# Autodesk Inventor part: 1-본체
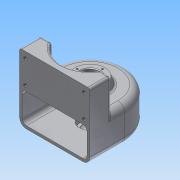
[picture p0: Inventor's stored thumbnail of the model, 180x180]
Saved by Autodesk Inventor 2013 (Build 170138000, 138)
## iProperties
Created: 2015-02
Part Number: 1-본체
Material: 알루미늄 6061
Document SubType Name: Modeling
Designer: Administrator
Density: 2.71 g/cm^3
Mass: 575.526 g
Surface Area: 706.56 cm^2
Volume: 212.371 cm^3
Author: Administrator
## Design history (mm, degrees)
sketch "스케치1" dims "d0" = 50
  geometry: L1 (50, 0)-(-50, 0); L2 (-50, 0)-(-50, -50); L3 (-50, -50)-(50, -50); L4 (50, -50)-(50, 0); 3 further points
  constraints: 8 end point, 2 coincident, 2 parallel, 1 horizontal, 1 horizontal alignment, 1 midpoint, 1 perpendicular, 2 other
  dimensions: "d3" = 50 distance of L3.end L1.start
extrude "돌출1" new body sketch "스케치1" distance "d4" = 50; taper "d5" = 0 deg
fillet "모깎기1" dims "d6" = 10
feature "쉘1" dims "d7" = 4
node "작업 평면1"
sketch "스케치2"
  geometry: L1 (-50, 0)-(-50, -50) reference; L2 (50, -50)-(50, 0) reference; L3 (50, -50)-(40, -50) reference; L4 (50, -50)-(-50, -50); L5 (-50, -50)-(-50, -20); L6 (50, -20)-(50, -50); L7 (-50, -20)-(-34.641, -20); L8 (34.641, -20)-(50, -20); A1 r 40 centre (0, 0) between (-34.641, -20) and (34.641, -20); 1 further point
  constraints: 10 end point, 3 parallel, 2 point on circle, 1 centre point, 1 coincident, 1 collinear, 1 horizontal, 1 perpendicular, 1 point on line
  dimensions: "d9" = 40 radius of A1; "d11" = 30 distance of L4.end L5.end
extrude "돌출2" join sketch "스케치2" stored distance "d12" = 50; taper "d13" = 0 deg
sketch "스케치3"
  geometry: C1 r 25 at (0, 0); A1 r 40 centre (0, 0) between (-34.641, -20) and (34.641, -20) reference
  constraints: 1 centre point, 1 coincident
  dimensions: "d14" = 50 diameter of C1
extrude "돌출3" join sketch "스케치3" distance "d16" = 10; taper "d17" = -20 deg
sketch "스케치4"
  geometry: C1 r 20 at (0, 0); A1 r 40 centre (0, 0) between (40, 0) and (-40, 0) reference
  constraints: 1 centre point, 1 coincident
  dimensions: "d18" = 40 diameter of C1
extrude "돌출4" join sketch "스케치4" distance "d20" = 9; taper "d21" = 0 deg
hole "구멍1" diameter "d24" = 20; stored, may be unused: countersink angle "d28" = 90 deg, drill point angle "d30" = 118 deg; dims "d22" = 10, "d23" = 10, "d25" = 6, "d26" = 28, "d27" = 10, "d29" = 8
sketch "스케치5"
  geometry: C1 r 20 at (0, 0) reference; A1 r 40 centre (0, 0) between (40, 0) and (-40, 0) reference
hole "구멍2" sketch "스케치5" at (0, 0) diameter "d31" = 20; stored, may be unused: countersink angle "d35" = 90 deg, drill point angle "d37" = 0 deg; dims "d32" = 6, "d33" = 28, "d34" = 8, "d36" = 10
sketch "스케치6" dims "d38" = 36
  geometry: C1 r 14 at (0, 0) reference; C2 r 21.36 at (0, 0) reference; 5 further points
  constraints: 2 vertical alignment, 1 coincident, 7 other
  dimensions: "d42" = 360 deg dimension on C1.centre point (0, 18) (derived)
hole "구멍3" sketch "스케치6" at (0, 18), (-18, 0), (18, 0), (0, -18) diameter "d44" = 2.459; stored, may be unused: countersink angle "d48" = 90 deg, drill point angle "d50" = 118 deg; dims "d45" = 6, "d46" = 28, "d47" = 8, "d49" = 9
sketch "스케치7"
  geometry: L1 (90, 95)-(-10, 95) reference; L2 (-1.75, 86)-(81.75, 86); L3 (81.75, 86)-(81.75, 53); L4 (81.75, 53)-(-1.75, 53); L5 (-1.75, 53)-(-1.75, 86); 3 further points
  constraints: 8 end point, 2 midpoint, 2 parallel, 1 horizontal, 1 perpendicular, 1 vertical alignment
  dimensions: "d51" = 83.5 distance of L2.start L2.end; "d53" = 33 distance of L4.end L2.start; "d54" = 9 distance between parallel lines of L2 L1
hole "구멍4" sketch "스케치7" at (-1.75, 86), (81.75, 86), (81.75, 53), (-1.75, 53) diameter "d55" = 5.134; stored, may be unused: countersink angle "d59" = 90 deg, drill point angle "d61" = 118 deg; dims "d56" = 10, "d57" = 28, "d58" = 8, "d60" = 13
node "작업 평면2"
sketch "스케치8"
  geometry: L1 (40, 0)-(-40, 0) reference; 2 further points
  constraints: 1 vertical alignment, 1 other
  dimensions: "d62" = 25 distance from line of L1 point (0, 25)
feature "엠보싱1" sketch "스케치8" dims "d0" = 50, "d3" = 50, "d63" = 0.5, "d64" = 0
chamfer "모따기1" distance "d65" = 1; stored, may be unused: second distance "d66" = 2, angle "d67" = 45 deg
fillet "모깎기2" dims "d68" = 3, "d69" = 0.3
fillet "모깎기3" dims "d70" = 3
node "솔리드1"
other parameters: "d8" = -95
